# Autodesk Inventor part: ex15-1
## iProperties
Shininess: 64.0
Length Units: 11272
Angle Units: 11279
Time Units: 11290
Mass Units: 11286
Length Display Precision: 3
Angle Display Precision: 2
Compacted: True
Part Number: ex15-1
Document SubType Name: Modeling
Created: 2002-09
Designer: Elise Moss
Density: 0.0
Volumn: 0.0
Area: 0.0
PropertySet Name: Model Information
Control State: 0
Master: False
Checked Out: False
Author: Elise Moss
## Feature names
1. Revolution1
2. Shell1
3. Hole1
4. Loft1
5. Sweep1
6. Coil1
